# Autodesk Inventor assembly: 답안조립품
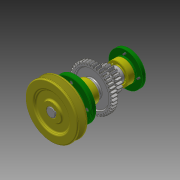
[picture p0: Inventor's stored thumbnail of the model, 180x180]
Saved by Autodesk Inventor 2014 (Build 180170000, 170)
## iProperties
Created: 2016-10
Part Number: 답안조립품
Document SubType Name: Assembly
Designer: USER
Author: USER
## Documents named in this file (14)
- C:\Users\USER\Desktop\461008V1014\답안조립품.iam
- C:\Users\USER\Desktop\461008V1014\본체.ipt
- C:\Users\USER\Desktop\461008V1014\앞커버.ipt
- C:\Users\USER\Desktop\461008V1014\뒤커버.ipt
- C:\Users\USER\Desktop\461008V1014\오일씰 28 40 8.ipt
- C:\Users\USER\Desktop\461008V1014\베어링 6203.ipt
- C:\Users\USER\Desktop\461008V1014\축.ipt
- C:\Users\USER\Desktop\461008V1014\스퍼기어.ipt
- C:\Users\USER\Desktop\461008V1014\키 - 6 x 6 x 22.ipt
- C:\Users\USER\Desktop\461008V1014\키 - 5 x 5 x 18.ipt
- C:\Users\USER\Desktop\461008V1014\멈춤나사 - M4x10.ipt
- C:\Users\USER\Desktop\461008V1014\V-벨트풀리.ipt
- C:\Users\USER\Desktop\461008V1014\볼트 M3 x 10.ipt
- C:\Users\USER\Desktop\461008V1014\볼트 M3 x 8.ipt
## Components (9 placed, 3 different names)
1. V-벨트풀리:1
2. ISO 4762 M3 x 10:1
3. ISO 4762 M3 x 10:2
4. ISO 4762 M3 x 10:3
5. ISO 4762 M3 x 10:4
6. ISO 4762 M3 x 8:1
7. ISO 4762 M3 x 8:2
8. ISO 4762 M3 x 8:3
9. ISO 4762 M3 x 8:4
